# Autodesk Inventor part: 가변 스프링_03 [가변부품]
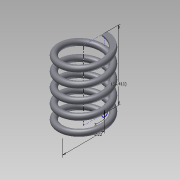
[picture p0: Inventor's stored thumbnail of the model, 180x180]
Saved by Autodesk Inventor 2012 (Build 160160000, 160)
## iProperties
Created: 2015-05
Part Number: 가변 스프링_03 [가변부품]
Material: 탄소강
Document SubType Name: Modeling
Designer: Administrator
Density: 7.87 g/cm^3
Mass: 18.8942 g
Surface Area: 32.5507 cm^2
Volume: 2.40079 cm^3
Author: Administrator
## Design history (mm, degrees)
sketch "스케치2"
  geometry: L1 (0, 0)-(11, 0); L2 (11, 0)-(11, 36.411); L3 (11, 36.411)-(0, 36.411); L4 (0, 36.411)-(0, 0); C1 r 1.5 at (11, 0)
  constraints: 8 end point, 2 parallel, 1 centre point, 1 coincident, 1 horizontal, 1 perpendicular
  dimensions: "d0" = 22 diameter of L2 L4; "d1" = 36.4112 distance of L1.end L2.end (derived); "d2" = 3 diameter of C1
feature "코일1" pitch "d3" = 10; turns "d5" = 5; dims "d4" = 36.4112 (= d1), "d6" = 0, angle "d7" = 90 deg, angle "d8" = 90 deg, "d9" = 0, "d10" = 0
sketch "스케치3"
  geometry: L1 (0, 12.5)-(0, 9.5) reference; 1 further point
  constraints: 1 vertical alignment
extrude "돌출1" cut sketch "스케치3" stored distance "d11" = 10; taper "d12" = 0 deg
node "작업 평면1"
sketch "스케치4"
  geometry: L1 (0, 12.5)-(0, 9.5) reference; 1 further point
  constraints: 1 vertical alignment
extrude "돌출2" cut sketch "스케치4" stored distance "d13" = 10; taper "d14" = 0 deg
node "솔리드1"
node "절단 모서리 투영1"
node "절단 모서리 투영2"
